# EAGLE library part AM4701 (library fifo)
FIFO
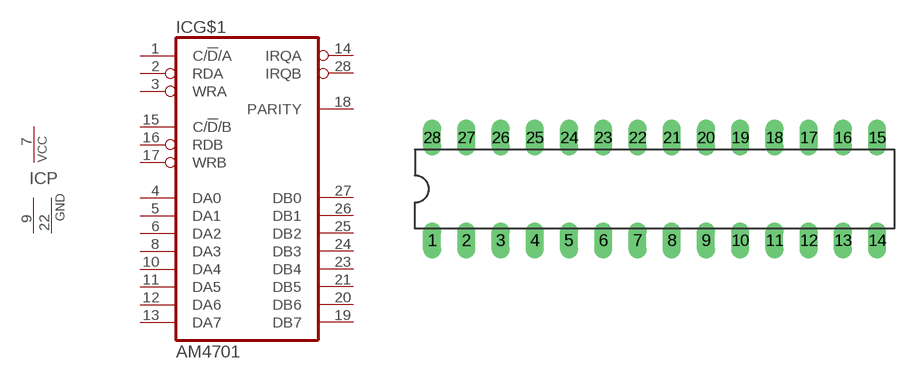
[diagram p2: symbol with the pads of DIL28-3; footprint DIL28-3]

Designator prefix IC; gates G$1=AM4701 P=PWR2GND

## AM4701 (OC_FARNELL: unknown; OC_NEWARK: unknown)  [DIL28-3]
1  G$1:C/!D!/A  in
2  G$1:RDA  in
3  G$1:WRA  in
4  G$1:DA0  in
5  G$1:DA1  in
6  G$1:DA2  in
7  P:VCC  pwr
8  G$1:DA3  in
9  P:GND  pwr
10  G$1:DA4  in
11  G$1:DA5  in
12  G$1:DA6  in
13  G$1:DA7  in
14  G$1:IRQA  out
15  G$1:C/!D!/B  in
16  G$1:RDB  in
17  G$1:WRB  in
18  G$1:PARITY
19  G$1:DB7  out
20  G$1:DB6  out
21  G$1:DB5  out
22  P:GND  pwr
23  G$1:DB4  out
24  G$1:DB3  out
25  G$1:DB2  out
26  G$1:DB1  out
27  G$1:DB0  out
28  G$1:IRQB  out

## Footprint DIL28-3 (pad centres in mm)
Dual In Line Package Small
drill 0.813 long: 1 -16.51,-3.81; 2 -13.97,-3.81; 3 -11.43,-3.81; 4 -8.89,-3.81; 5 -6.35,-3.81; 6 -3.81,-3.81; 7 -1.27,-3.81; 8 1.27,-3.81; 9 3.81,-3.81; 10 6.35,-3.81; 11 8.89,-3.81; 12 11.43,-3.81; 13 13.97,-3.81; 14 16.51,-3.81; 15 16.51,3.81; 16 13.97,3.81; 17 11.43,3.81; 18 8.89,3.81; 19 6.35,3.81; 20 3.81,3.81; 21 1.27,3.81; 22 -1.27,3.81; 23 -3.81,3.81; 24 -6.35,3.81; 25 -8.89,3.81; 26 -11.43,3.81; 27 -13.97,3.81; 28 -16.51,3.81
